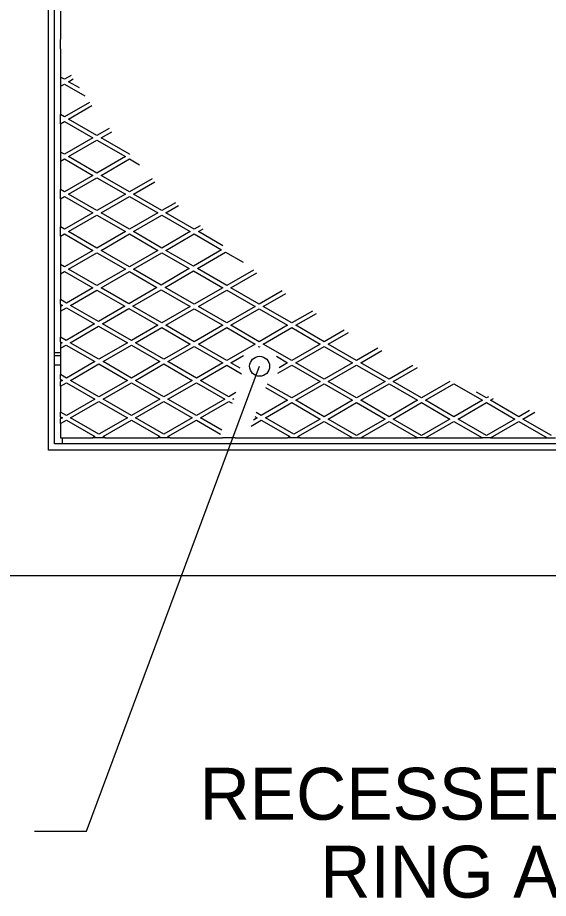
# Model space of a CAD drawing. Extents: x 99862 to 103151, y 100000 to 105076.
# Drawn here: x 100100.8 to 100264.4, y 100268.6 to 100539.9 of the extents above; entities that cross this region are included whole.
import ezdxf

# ---------------------------------------------------------------- set-up
doc = ezdxf.new("R2010")
doc.units = 0
for name, color, linetype in [('Level 15', 7, 'Continuous'), ('Level 20', 7, 'Continuous'), ('Level 3', 7, 'Continuous'), ('Level 4', 7, 'Continuous'), ('Level 5', 7, 'Continuous')]:
    doc.layers.add(name, color=color, linetype=linetype)

msp = doc.modelspace()

# ---------------------------------------------------------------- linework, layer by layer
at = {"layer": 'Level 15'}
for p, q in [((100122.05, 100289.35), (100175.4, 100432.53)), ((100106.05, 100289.35), (100122.05, 100289.35))]:
    msp.add_line(p, q, dxfattribs=at)
msp.add_circle((100175.4, 100432.53), 3.08, dxfattribs=at)
at = {"layer": 'Level 3'}
for p, q in [((100110.32, 100406.73), (100110.32, 100649.23)), ((100114.69, 100408.61), (100114.69, 100410.48)), ((100479.07, 100406.73), (100110.32, 100406.73)), ((100514.69, 100367.98), (100074.69, 100367.98))]:
    msp.add_line(p, q, dxfattribs=at)
at = {"layer": 'Level 4'}
for p, q in [((100112.19, 100408.61), (100112.19, 100612.36)), ((100477.19, 100408.61), (100112.19, 100408.61))]:
    msp.add_line(p, q, dxfattribs=at)
for points, degree in [([(100112.19, 100436.73), (100112.22, 100436.73), (100112.25, 100436.73), (100112.28, 100436.73)], 2), ([(100114.07, 100435.8), (100114, 100435.8), (100113.81, 100435.8), (100113.48, 100435.8), (100113.08, 100435.8), (100112.68, 100435.8), (100112.39, 100435.8), (100112.22, 100435.8), (100112.19, 100435.8)], 3), ([(100112.28, 100436.73), (100112.35, 100436.73), (100112.48, 100436.73), (100112.62, 100436.73), (100112.68, 100436.73)], 3), ([(100112.68, 100436.73), (100112.75, 100436.73), (100112.88, 100436.73), (100113.01, 100436.73), (100113.08, 100436.73)], 3), ([(100113.08, 100436.73), (100113.15, 100436.73), (100113.28, 100436.73), (100113.41, 100436.73), (100113.48, 100436.73)], 3), ([(100113.48, 100436.73), (100113.55, 100436.73), (100113.68, 100436.73), (100113.81, 100436.73), (100113.88, 100436.73)], 3), ([(100113.88, 100436.73), (100113.94, 100436.73), (100114, 100436.73), (100114.07, 100436.73)], 2), ([(100112.19, 100432.99), (100112.22, 100432.99), (100112.25, 100432.99), (100112.28, 100432.99)], 2), ([(100112.28, 100432.99), (100112.35, 100432.99), (100112.48, 100432.99), (100112.62, 100432.99), (100112.68, 100432.99)], 3), ([(100112.68, 100432.99), (100112.75, 100432.99), (100112.88, 100432.99), (100113.01, 100432.99), (100113.08, 100432.99)], 3), ([(100113.08, 100432.99), (100113.15, 100432.99), (100113.28, 100432.99), (100113.41, 100432.99), (100113.48, 100432.99)], 3), ([(100113.48, 100432.99), (100113.55, 100432.99), (100113.68, 100432.99), (100113.81, 100432.99), (100113.88, 100432.99)], 3), ([(100113.88, 100432.99), (100113.94, 100432.99), (100114, 100432.99), (100114.07, 100432.99)], 2)]:
    msp.add_open_spline(points, degree=degree, dxfattribs=at)
at = {"layer": 'Level 5'}
for p, q in [((100114.07, 100541.87), (100114.07, 100533.17)), ((100114.07, 100530.33), (100114.07, 100533.17)), ((100114.07, 100530.33), (100114.07, 100521.63)), ((100117.31, 100522.09), (100115.28, 100520.92)), ((100114.07, 100521.63), (100114.07, 100518.78)), ((100115.28, 100520.92), (100114.07, 100521.63)), ((100114.07, 100518.78), (100115.28, 100519.48)), ((100115.28, 100519.48), (100121.53, 100515.88)), ((100116.53, 100520.2), (100118, 100521.05)), ((100119.86, 100518.28), (100116.53, 100520.2)), ((100114.07, 100518.78), (100114.07, 100510.08)), ((100122.98, 100513.82), (100115.28, 100509.38)), ((100116.53, 100508.66), (100123.72, 100512.81)), ((100114.07, 100507.23), (100114.07, 100510.08)), ((100115.28, 100509.38), (100114.07, 100510.08)), ((100125.28, 100503.6), (100116.53, 100508.66)), ((100114.07, 100507.23), (100115.28, 100507.93)), ((100114.07, 100507.23), (100114.07, 100498.53)), ((100115.28, 100507.93), (100124.03, 100502.88)), ((100129.03, 100505.77), (100125.28, 100503.6)), ((100124.03, 100502.88), (100115.28, 100497.83)), ((100126.53, 100502.88), (100129.82, 100504.78)), ((100135.28, 100497.83), (100126.53, 100502.88)), ((100116.53, 100497.11), (100125.28, 100502.16)), ((100125.28, 100502.16), (100134.03, 100497.11)), ((100114.07, 100498.53), (100114.07, 100495.69)), ((100115.28, 100497.83), (100114.07, 100498.53)), ((100135.46, 100497.93), (100135.28, 100497.83)), ((100114.07, 100495.69), (100115.28, 100496.39)), ((100114.07, 100495.69), (100114.07, 100486.98)), ((100115.28, 100496.39), (100124.03, 100491.34)), ((100125.28, 100492.06), (100116.53, 100497.11)), ((100134.03, 100497.11), (100125.28, 100492.06)), ((100126.53, 100491.34), (100135.28, 100496.39)), ((100135.28, 100496.39), (100138.36, 100494.61)), ((100124.03, 100491.34), (100115.28, 100486.28)), ((100116.53, 100485.56), (100125.28, 100490.61)), ((100125.28, 100490.61), (100134.03, 100485.56)), ((100135.28, 100486.28), (100126.53, 100491.34)), ((100142.27, 100490.32), (100135.28, 100486.28)), ((100136.53, 100485.56), (100143.15, 100489.38)), ((100114.07, 100484.14), (100114.07, 100486.98)), ((100115.28, 100486.28), (100114.07, 100486.98)), ((100114.07, 100484.14), (100115.28, 100484.84)), ((100114.07, 100484.14), (100114.07, 100475.44)), ((100115.28, 100484.84), (100124.03, 100479.79)), ((100125.28, 100480.51), (100116.53, 100485.56)), ((100134.03, 100485.56), (100125.28, 100480.51)), ((100126.53, 100479.79), (100135.28, 100484.84)), ((100135.28, 100484.84), (100144.03, 100479.79)), ((100145.28, 100480.51), (100136.53, 100485.56)), ((100149.47, 100482.93), (100145.28, 100480.51)), ((100146.53, 100479.79), (100150.4, 100482.02)), ((100124.03, 100479.79), (100115.28, 100474.74)), ((100116.53, 100474.01), (100125.28, 100479.07)), ((100125.28, 100479.07), (100134.03, 100474.01)), ((100135.28, 100474.74), (100126.53, 100479.79)), ((100144.03, 100479.79), (100135.28, 100474.74)), ((100136.53, 100474.01), (100145.28, 100479.07)), ((100145.28, 100479.07), (100154.03, 100474.01)), ((100155.28, 100474.74), (100146.53, 100479.79)), ((100157.06, 100475.76), (100155.28, 100474.74)), ((100114.07, 100472.59), (100114.07, 100475.44)), ((100115.28, 100474.74), (100114.07, 100475.44)), ((100114.07, 100472.59), (100115.28, 100473.29)), ((100115.28, 100473.29), (100124.03, 100468.24)), ((100125.28, 100468.96), (100116.53, 100474.01)), ((100134.03, 100474.01), (100125.28, 100468.96)), ((100126.53, 100468.24), (100135.28, 100473.29)), ((100135.28, 100473.29), (100144.03, 100468.24)), ((100145.28, 100468.96), (100136.53, 100474.01)), ((100154.03, 100474.01), (100145.28, 100468.96)), ((100146.53, 100468.24), (100155.28, 100473.29)), ((100155.28, 100473.29), (100163.69, 100468.44)), ((100156.53, 100474.01), (100158.04, 100474.89)), ((100164.1, 100469.65), (100156.53, 100474.01)), ((100114.07, 100472.59), (100114.07, 100463.89)), ((100124.03, 100468.24), (100115.28, 100463.19)), ((100116.53, 100462.47), (100125.28, 100467.52)), ((100125.28, 100467.52), (100134.03, 100462.47)), ((100135.28, 100463.19), (100126.53, 100468.24)), ((100144.03, 100468.24), (100135.28, 100463.19)), ((100136.53, 100462.47), (100145.28, 100467.52)), ((100145.28, 100467.52), (100153.74, 100462.64)), ((100154.98, 100463.36), (100146.53, 100468.24)), ((100163.69, 100468.44), (100154.98, 100463.36)), ((100156.23, 100462.64), (100164.93, 100467.72)), ((100164.93, 100467.72), (100170.29, 100464.63)), ((100114.07, 100463.89), (100114.07, 100461.04)), ((100115.28, 100463.19), (100114.07, 100463.89)), ((100125.28, 100457.42), (100116.53, 100462.47)), ((100134.03, 100462.47), (100125.28, 100457.42)), ((100145.03, 100457.56), (100136.53, 100462.47)), ((100153.74, 100462.64), (100145.03, 100457.56)), ((100165.28, 100457.42), (100156.23, 100462.64)), ((100173.49, 100462.16), (100165.28, 100457.42)), ((100114.07, 100461.04), (100115.28, 100461.75)), ((100114.07, 100461.04), (100114.07, 100453.07)), ((100115.28, 100461.75), (100124.03, 100456.69)), ((100126.53, 100456.69), (100135.28, 100461.75)), ((100135.28, 100461.75), (100143.78, 100456.84)), ((100146.27, 100456.84), (100154.98, 100461.92)), ((100154.98, 100461.92), (100164.03, 100456.69)), ((100166.53, 100456.69), (100174.58, 100461.34)), ((100124.03, 100456.69), (100115.91, 100452)), ((100135.07, 100451.76), (100126.53, 100456.69)), ((100143.78, 100456.84), (100135.07, 100451.76)), ((100155.28, 100451.64), (100146.27, 100456.84)), ((100164.03, 100456.69), (100155.28, 100451.64)), ((100175.28, 100451.64), (100166.53, 100456.69)), ((100117.16, 100451.28), (100125.28, 100455.97)), ((100125.28, 100455.97), (100133.83, 100451.04)), ((100136.32, 100451.04), (100145.03, 100456.12)), ((100145.03, 100456.12), (100154.03, 100450.92)), ((100156.53, 100450.92), (100165.28, 100455.97)), ((100165.28, 100455.97), (100174.03, 100450.92)), ((100182.36, 100455.73), (100175.28, 100451.64)), ((100176.53, 100450.92), (100183.5, 100454.94)), ((100114.07, 100451.62), (100114.07, 100453.07)), ((100115.91, 100452), (100114.07, 100453.07)), ((100114.07, 100451.62), (100114.66, 100451.28)), ((100114.07, 100451.62), (100114.07, 100450.94)), ((100114.66, 100451.28), (100114.07, 100450.94)), ((100125.74, 100446.32), (100117.16, 100451.28)), ((100114.07, 100450.94), (100114.07, 100449.5)), ((100114.07, 100449.5), (100115.91, 100450.56)), ((100114.07, 100449.5), (100114.07, 100441.52)), ((100115.91, 100450.56), (100124.5, 100445.6)), ((100133.83, 100451.04), (100125.74, 100446.32)), ((100126.99, 100445.6), (100135.08, 100450.32)), ((100135.08, 100450.32), (100144.03, 100445.15)), ((100145.28, 100445.87), (100136.32, 100451.04)), ((100154.03, 100450.92), (100145.28, 100445.87)), ((100146.53, 100445.15), (100155.28, 100450.2)), ((100155.28, 100450.2), (100164.03, 100445.15)), ((100165.28, 100445.87), (100156.53, 100450.92)), ((100174.03, 100450.92), (100165.28, 100445.87)), ((100166.53, 100445.15), (100175.28, 100450.2)), ((100175.28, 100450.2), (100184.03, 100445.15)), ((100185.28, 100445.87), (100176.53, 100450.92)), ((100191.68, 100449.56), (100185.28, 100445.87)), ((100186.53, 100445.15), (100192.88, 100448.81)), ((100124.5, 100445.6), (100115.79, 100440.52)), ((100117.04, 100439.8), (100125.75, 100444.88)), ((100125.75, 100444.88), (100134.66, 100439.73)), ((100135.91, 100440.46), (100126.99, 100445.6)), ((100144.03, 100445.15), (100135.91, 100440.46)), ((100137.16, 100439.73), (100145.28, 100444.43)), ((100145.28, 100444.43), (100154.03, 100439.37)), ((100155.28, 100440.1), (100146.53, 100445.15)), ((100164.03, 100445.15), (100155.28, 100440.1)), ((100156.53, 100439.37), (100165.28, 100444.43)), ((100165.28, 100444.43), (100174.03, 100439.37)), ((100175.28, 100440.1), (100166.53, 100445.15)), ((100184.03, 100445.15), (100175.28, 100440.1)), ((100176.53, 100439.37), (100185.28, 100444.43)), ((100185.28, 100444.43), (100194.03, 100439.37)), ((100195.28, 100440.1), (100186.53, 100445.15)), ((100201.48, 100443.67), (100195.28, 100440.1)), ((100114.07, 100440.07), (100114.07, 100441.52)), ((100115.79, 100440.52), (100114.07, 100441.52)), ((100196.53, 100439.37), (100202.74, 100442.96)), ((100114.07, 100440.07), (100114.55, 100439.8)), ((100114.07, 100440.07), (100114.07, 100439.52)), ((100114.55, 100439.8), (100114.07, 100439.52)), ((100114.07, 100439.52), (100114.07, 100438.07)), ((100114.07, 100438.07), (100115.79, 100439.08)), ((100114.07, 100438.07), (100114.07, 100429.97)), ((100115.79, 100439.08), (100124.66, 100433.96)), ((100125.91, 100434.68), (100117.04, 100439.8)), ((100134.66, 100439.73), (100125.91, 100434.68)), ((100127.16, 100433.96), (100135.91, 100439.01)), ((100135.91, 100439.01), (100144.66, 100433.96)), ((100145.91, 100434.68), (100137.16, 100439.73)), ((100154.03, 100439.37), (100145.91, 100434.68)), ((100147.16, 100433.96), (100155.28, 100438.65)), ((100155.28, 100438.65), (100164.03, 100433.6)), ((100165.28, 100434.32), (100156.53, 100439.37)), ((100174.03, 100439.37), (100165.28, 100434.32)), ((100175.05, 100438.52), (100175.28, 100438.65)), ((100175.28, 100438.65), (100175.49, 100438.53)), ((100185.28, 100434.32), (100176.53, 100439.37)), ((100194.03, 100439.37), (100185.28, 100434.32)), ((100186.53, 100433.6), (100195.28, 100438.65)), ((100195.28, 100438.65), (100204.03, 100433.6)), ((100205.28, 100434.32), (100196.53, 100439.37)), ((100211.78, 100438.07), (100205.28, 100434.32)), ((100166.53, 100433.6), (100170.39, 100435.83)), ((100180.55, 100435.61), (100184.03, 100433.6)), ((100206.53, 100433.6), (100213.1, 100437.39)), ((100124.66, 100433.96), (100115.91, 100428.91)), ((100117.16, 100428.19), (100125.91, 100433.24)), ((100125.91, 100433.24), (100134.66, 100428.19)), ((100135.91, 100428.91), (100127.16, 100433.96)), ((100144.66, 100433.96), (100135.91, 100428.91)), ((100137.16, 100428.19), (100145.91, 100433.24)), ((100145.91, 100433.24), (100154.66, 100428.19)), ((100155.91, 100428.91), (100147.16, 100433.96)), ((100164.03, 100433.6), (100155.91, 100428.91)), ((100157.16, 100428.19), (100165.28, 100432.88)), ((100165.28, 100432.88), (100169.86, 100430.24)), ((100169.43, 100431.93), (100166.53, 100433.6)), ((100181.02, 100430.42), (100185.28, 100432.88)), ((100184.03, 100433.6), (100181.39, 100432.07)), ((100185.28, 100432.88), (100194.03, 100427.83)), ((100195.28, 100428.55), (100186.53, 100433.6)), ((100204.03, 100433.6), (100195.28, 100428.55)), ((100196.53, 100427.83), (100205.28, 100432.88)), ((100205.28, 100432.88), (100214.03, 100427.83)), ((100215.28, 100428.55), (100206.53, 100433.6)), ((100222.6, 100432.77), (100215.28, 100428.55)), ((100114.07, 100428.53), (100114.07, 100429.97)), ((100115.91, 100428.91), (100114.07, 100429.97)), ((100216.53, 100427.83), (100223.99, 100432.13)), ((100114.07, 100428.53), (100114.66, 100428.19)), ((100114.07, 100428.53), (100114.07, 100427.85)), ((100114.66, 100428.19), (100114.07, 100427.85)), ((100114.07, 100426.4), (100114.07, 100427.85)), ((100114.07, 100426.4), (100115.91, 100427.47)), ((100115.91, 100427.47), (100124.66, 100422.41)), ((100125.91, 100423.14), (100117.16, 100428.19)), ((100134.66, 100428.19), (100125.91, 100423.14)), ((100127.16, 100422.41), (100135.91, 100427.47)), ((100135.91, 100427.47), (100144.66, 100422.41)), ((100145.91, 100423.14), (100137.16, 100428.19)), ((100154.66, 100428.19), (100145.91, 100423.14)), ((100147.16, 100422.41), (100155.91, 100427.47)), ((100155.91, 100427.47), (100164.66, 100422.41)), ((100165.91, 100423.14), (100157.16, 100428.19)), ((100185.28, 100422.77), (100177.86, 100427.06)), ((100194.03, 100427.83), (100185.28, 100422.77)), ((100186.53, 100422.05), (100195.28, 100427.1)), ((100195.28, 100427.1), (100204.03, 100422.05)), ((100205.28, 100422.77), (100196.53, 100427.83)), ((100214.03, 100427.83), (100205.28, 100422.77)), ((100206.53, 100422.05), (100215.28, 100427.1)), ((100215.28, 100427.1), (100224.03, 100422.05)), ((100225.28, 100422.77), (100216.53, 100427.83)), ((100233.99, 100427.8), (100225.28, 100422.77)), ((100226.53, 100422.05), (100235.28, 100427.1)), ((100235.28, 100427.1), (100244.03, 100422.05)), ((100114.07, 100426.4), (100114.07, 100418.42)), ((100168.11, 100424.41), (100165.91, 100423.14)), ((100177.23, 100425.98), (100184.03, 100422.05)), ((100245.28, 100422.77), (100242.17, 100424.57)), ((100124.66, 100422.41), (100115.91, 100417.36)), ((100117.16, 100416.64), (100125.91, 100421.69)), ((100125.91, 100421.69), (100134.66, 100416.64)), ((100135.91, 100417.36), (100127.16, 100422.41)), ((100144.66, 100422.41), (100135.91, 100417.36)), ((100137.16, 100416.64), (100145.91, 100421.69)), ((100145.91, 100421.69), (100154.66, 100416.64)), ((100155.91, 100417.36), (100147.16, 100422.41)), ((100164.66, 100422.41), (100155.91, 100417.36)), ((100157.16, 100416.64), (100165.91, 100421.69)), ((100165.91, 100421.69), (100166.89, 100421.13)), ((100167.16, 100422.41), (100167.42, 100422.57)), ((100167.33, 100422.32), (100167.16, 100422.41)), ((100184.03, 100422.05), (100175.91, 100417.36)), ((100195.28, 100417), (100186.53, 100422.05)), ((100204.03, 100422.05), (100195.28, 100417)), ((100215.28, 100417), (100206.53, 100422.05)), ((100224.03, 100422.05), (100215.28, 100417)), ((100235.28, 100417), (100226.53, 100422.05)), ((100244.03, 100422.05), (100235.28, 100417)), ((100245.96, 100423.17), (100245.28, 100422.77)), ((100246.53, 100422.05), (100247.5, 100422.61)), ((100255.28, 100417), (100246.53, 100422.05)), ((100177.16, 100416.64), (100185.28, 100421.33)), ((100185.28, 100421.33), (100194.03, 100416.28)), ((100196.53, 100416.28), (100205.28, 100421.33)), ((100205.28, 100421.33), (100214.03, 100416.28)), ((100216.53, 100416.28), (100225.28, 100421.33)), ((100225.28, 100421.33), (100234.03, 100416.28)), ((100236.53, 100416.28), (100245.28, 100421.33)), ((100245.28, 100421.33), (100254.03, 100416.28)), ((100258.57, 100418.9), (100255.28, 100417)), ((100114.07, 100416.98), (100114.07, 100418.42)), ((100115.91, 100417.36), (100114.07, 100418.42)), ((100114.07, 100416.98), (100114.66, 100416.64)), ((100114.07, 100416.98), (100114.07, 100416.3)), ((100114.66, 100416.64), (100114.07, 100416.3)), ((100114.07, 100414.86), (100114.07, 100416.3)), ((100125.91, 100411.59), (100117.16, 100416.64)), ((100134.66, 100416.64), (100125.91, 100411.59)), ((100145.91, 100411.59), (100137.16, 100416.64)), ((100154.66, 100416.64), (100145.91, 100411.59)), ((100163.79, 100412.81), (100157.16, 100416.64)), ((100174.66, 100416.64), (100173.5, 100415.97)), ((100173.91, 100417.07), (100174.66, 100416.64)), ((100175.91, 100417.36), (100174.35, 100418.26)), ((100185.91, 100411.59), (100177.16, 100416.64)), ((100194.03, 100416.28), (100185.91, 100411.59)), ((100205.28, 100411.23), (100196.53, 100416.28)), ((100214.03, 100416.28), (100205.28, 100411.23)), ((100225.28, 100411.23), (100216.53, 100416.28)), ((100234.03, 100416.28), (100225.28, 100411.23)), ((100245.28, 100411.23), (100236.53, 100416.28)), ((100254.03, 100416.28), (100245.28, 100411.23)), ((100256.53, 100416.28), (100260.2, 100418.39)), ((100265.28, 100411.23), (100256.53, 100416.28)), ((100114.07, 100414.86), (100115.91, 100415.92)), ((100114.07, 100414.86), (100114.07, 100410.48)), ((100115.91, 100415.92), (100124.66, 100410.87)), ((100127.16, 100410.87), (100135.91, 100415.92)), ((100135.91, 100415.92), (100144.66, 100410.87)), ((100147.16, 100410.87), (100155.91, 100415.92)), ((100155.91, 100415.92), (100163.34, 100411.62)), ((100172.82, 100414.13), (100175.91, 100415.92)), ((100175.91, 100415.92), (100184.66, 100410.87)), ((100187.16, 100410.87), (100195.28, 100415.56)), ((100195.28, 100415.56), (100204.03, 100410.51)), ((100206.53, 100410.51), (100215.28, 100415.56)), ((100215.28, 100415.56), (100224.03, 100410.51)), ((100226.53, 100410.51), (100235.28, 100415.56)), ((100235.28, 100415.56), (100244.03, 100410.51)), ((100246.53, 100410.51), (100255.28, 100415.56)), ((100255.28, 100415.56), (100264.03, 100410.51)), ((100124.66, 100410.87), (100124, 100410.48)), ((100127.82, 100410.48), (100127.16, 100410.87)), ((100144.66, 100410.87), (100144, 100410.48)), ((100147.82, 100410.48), (100147.16, 100410.87)), ((100184.66, 100410.87), (100184, 100410.48)), ((100187.82, 100410.48), (100187.16, 100410.87)), ((100114.07, 100410.48), (100124, 100410.48)), ((100127.82, 100410.48), (100124, 100410.48)), ((100127.82, 100410.48), (100144, 100410.48)), ((100147.82, 100410.48), (100144, 100410.48)), ((100147.82, 100410.48), (100164, 100410.48)), ((100167.82, 100410.48), (100164, 100410.48)), ((100167.82, 100410.48), (100184, 100410.48)), ((100187.82, 100410.48), (100184, 100410.48)), ((100187.82, 100410.48), (100204, 100410.48)), ((100204.03, 100410.51), (100204, 100410.48)), ((100204, 100410.48), (100206.57, 100410.48)), ((100206.57, 100410.48), (100206.53, 100410.51)), ((100206.57, 100410.48), (100224, 100410.48)), ((100224.03, 100410.51), (100224, 100410.48)), ((100226.57, 100410.48), (100224, 100410.48)), ((100226.57, 100410.48), (100226.53, 100410.51)), ((100226.57, 100410.48), (100244, 100410.48)), ((100244.03, 100410.51), (100244, 100410.48)), ((100246.57, 100410.48), (100244, 100410.48)), ((100246.57, 100410.48), (100246.53, 100410.51)), ((100246.57, 100410.48), (100264, 100410.48)), ((100264.03, 100410.51), (100264, 100410.48)), ((100264, 100410.48), (100266.57, 100410.48))]:
    msp.add_line(p, q, dxfattribs=at)

# ---------------------------------------------------------------- texts
at = {"layer": 'Level 20'}
for s, p in [('RECESSED LIFTING', (100156.92, 100292.86)), ('RING AND LOCK', (100194.09, 100268.86))]:
    msp.add_text(s, height=16, rotation=360, dxfattribs=at).set_placement(p)

doc.saveas('drawing.dxf')
